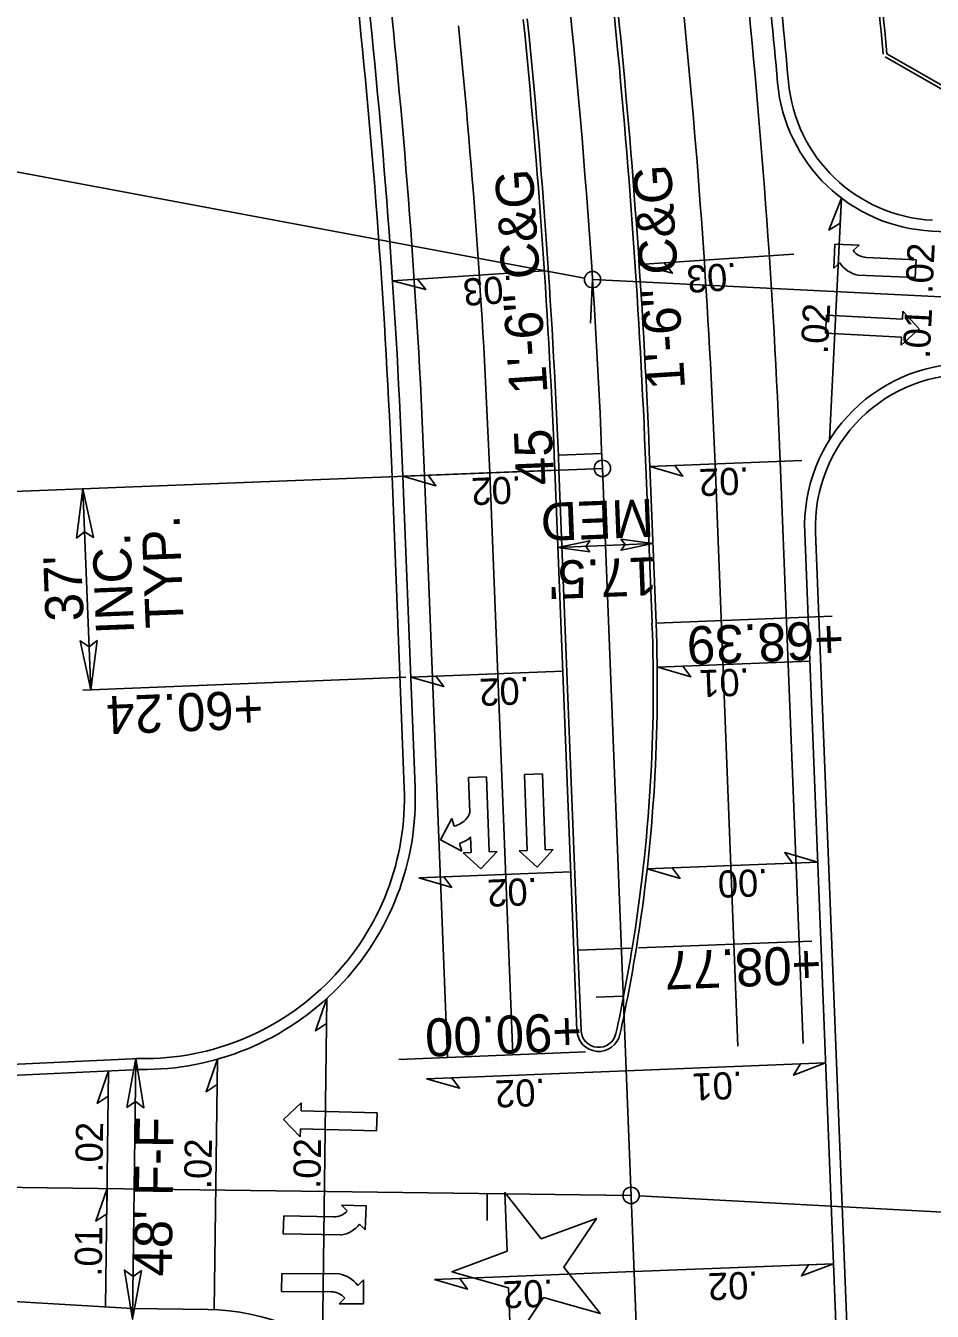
# Model space of a CAD drawing. Extents: x 1627861 to 1629601, y 761281 to 766239.
# Drawn here: x 1628267 to 1628433.8, y 764815.3 to 765051.9 of the extents above; entities that cross this region are included whole.
import ezdxf

# ---------------------------------------------------------------- set-up
doc = ezdxf.new("R2010")
doc.units = 0
for name, color, linetype in [('Exist Property Tie Line Leader', 7, 'Continuous'), ('Exist Property Tie Line Text', 7, 'Continuous'), ('Exist Right of Way Line Leader', 7, 'Continuous'), ('Exist Right of Way Monument Leader', 7, 'Continuous'), ('Exist Right of Way Monument Text', 7, 'Continuous'), ('Exist Utilities Gas Meter CELL', 7, 'Continuous'), ('Exist Utilities Gas Meter Cogo Elevation', 7, 'Continuous'), ('Exist Utilities Gas Meter Cogo Number', 7, 'Continuous'), ('Exist Utilities Gas UG Line', 7, 'Continuous'), ('Exist Utilities Other Unknown UG SUE Text', 7, 'Continuous'), ('Exist Utilities Power UG Cable SUE LOS B Cogo Elevation', 7, 'Continuous'), ('Exist Utilities Power UG Cable SUE LOS B Cogo Point CELL', 7, 'Continuous'), ('Exist Utilities Telephone UG Cable SUE LOS B Cogo Number', 7, 'Continuous'), ('Exist Utilities Water Meter Cogo Elevation', 7, 'Continuous'), ('Exist Utilities Water UG Line SUE LOS B Cogo Number', 7, 'Continuous'), ('Matchline', 7, 'Continuous'), ('Scratch_Level_0', 7, 'Continuous'), ('Typical Terminator CELL', 7, 'Continuous')]:
    doc.layers.add(name, color=color, linetype=linetype)

msp = doc.modelspace()

# ---------------------------------------------------------------- linework, layer by layer
at = {"layer": 'Exist Property Tie Line Text'}
for p, q in [((1628376.95, 764873.29), (1628371.95, 764873.09)), ((1628351.94, 764836.96), (1628351.88, 764831.96))]:
    msp.add_line(p, q, dxfattribs=at)
at = {"layer": 'Exist Right of Way Line Leader'}
for p, q in [((1628369.83, 765005.5), (1628135.9, 765049.17)), ((1628373.12, 764970.45), (1628128.07, 764960.79)), ((1628379.89, 764836.53), (1628534.55, 764828.18))]:
    msp.add_line(p, q, dxfattribs=at)
for centre in [(1628371.3, 765005.2), (1628371.3, 765005.2), (1628373.12, 764970.45), (1628378.39, 764836.61)]:
    msp.add_circle(centre, 1.5, dxfattribs=at)
at = {"layer": 'Exist Right of Way Monument Leader'}
for p, q in [((1628415.72, 765007.3), (1628415.87, 765011.7)), ((1628415.87, 765011.7), (1628420.37, 765011.54)), ((1628420.37, 765011.54), (1628419.27, 765010.54)), ((1628416.82, 765008.3), (1628415.72, 765007.3)), ((1628421.72, 765009.28), (1628430.86, 765008.87)), ((1628430.86, 765008.87), (1628430.71, 765005.57)), ((1628430.71, 765005.57), (1628420.17, 765006.05)), ((1628414.21, 764995.33), (1628414.38, 764998.63)), ((1628414.38, 764998.63), (1628428.36, 764997.9)), ((1628428.36, 764997.9), (1628428.44, 764999.4)), ((1628428.44, 764999.4), (1628431.43, 764996.14)), ((1628428.19, 764994.61), (1628414.21, 764995.33)), ((1628431.43, 764996.14), (1628428.11, 764993.11)), ((1628428.11, 764993.11), (1628428.19, 764994.61)), ((1628348.48, 764913.53), (1628351.78, 764913.65)), ((1628348.71, 764907.09), (1628348.48, 764913.53)), ((1628351.78, 764913.65), (1628352.27, 764899.86)), ((1628358.78, 764914.11), (1628362.08, 764914.22)), ((1628359.29, 764900.12), (1628358.78, 764914.11)), ((1628362.08, 764914.22), (1628362.58, 764900.23)), ((1628343.34, 764902.04), (1628345.4, 764905.97)), ((1628345.4, 764905.97), (1628345.85, 764904.58)), ((1628347.27, 764899.98), (1628343.34, 764902.04)), ((1628346.82, 764901.42), (1628347.27, 764899.98)), ((1628348.98, 764899.74), (1628348.87, 764902.59)), ((1628347.48, 764899.69), (1628348.98, 764899.74)), ((1628350.74, 764896.7), (1628347.48, 764899.69)), ((1628353.77, 764899.92), (1628350.74, 764896.7)), ((1628352.27, 764899.86), (1628353.77, 764899.92)), ((1628357.79, 764900.06), (1628359.29, 764900.12)), ((1628361.1, 764897.03), (1628357.79, 764900.06)), ((1628364.08, 764900.29), (1628361.1, 764897.03)), ((1628362.58, 764900.23), (1628364.08, 764900.29)), ((1628314.45, 764850.56), (1628317.69, 764853.67)), ((1628317.69, 764853.67), (1628317.65, 764852.17)), ((1628317.65, 764852.17), (1628331.64, 764851.78)), ((1628331.64, 764851.78), (1628331.55, 764848.48)), ((1628317.51, 764847.38), (1628314.45, 764850.56)), ((1628317.55, 764848.87), (1628317.51, 764847.38)), ((1628331.55, 764848.48), (1628317.55, 764848.87)), ((1628329.61, 764834.66), (1628325.11, 764834.81)), ((1628325.11, 764834.81), (1628326.14, 764833.74)), ((1628329.46, 764830.26), (1628329.61, 764834.66)), ((1628314.46, 764832.86), (1628314.39, 764829.56)), ((1628323.61, 764832.65), (1628314.46, 764832.86)), ((1628314.39, 764829.56), (1628324.93, 764829.32)), ((1628328.43, 764831.34), (1628329.46, 764830.26)), ((1628314.08, 764818.9), (1628314.1, 764822.2)), ((1628314.1, 764822.2), (1628324.65, 764822.14)), ((1628328.08, 764820.02), (1628329.14, 764821.06)), ((1628329.14, 764821.06), (1628329.16, 764816.66)), ((1628323.23, 764818.84), (1628314.08, 764818.9)), ((1628324.66, 764816.64), (1628325.72, 764817.68)), ((1628329.16, 764816.66), (1628324.66, 764816.64))]:
    msp.add_line(p, q, dxfattribs=at)
for centre, radius, start, end in [((1628421.85, 765012.54), 3.27, 217.7364, 267.3946), ((1628421.19, 765011.18), 5.25, 213.4068, 258.7185), ((1628344.79, 764908.89), 4.43, 283.7683, 314.6218), ((1628346.25, 764907.64), 2.52, 311.1317, 347.4437), ((1628345.77, 764905.74), 4.43, 283.6494, 314.528), ((1628323.69, 764835.9), 3.27, 268.6786, 318.3368), ((1628324.26, 764834.51), 5.25, 277.3547, 322.6664), ((1628323.82, 764816.96), 5.25, 35.6789, 80.9906), ((1628323.22, 764815.59), 3.27, 40.0085, 89.6667)]:
    msp.add_arc(centre, radius, start, end, dxfattribs=at)
at = {"layer": 'Exist Right of Way Monument Text'}
for p, q in [((1628433.78, 765014.15), (1628442.99, 765013.69)), ((1628367.86, 764881.7), (1628364.37, 764970.11)), ((1628383, 764941.97), (1628381.86, 764970.8)), ((1628338.65, 764911.76), (1628336.39, 764969)), ((1628424.43, 764601.84), (1628410.36, 764958.58)), ((1628242.2, 764857.68), (1628288.04, 764859.79)), ((1628287.23, 764859.8), (1628288.04, 764859.79)), ((1628286.66, 764815.8), (1628241.69, 764818.41)), ((1628286.66, 764815.8), (1628300.5, 764815.62))]:
    msp.add_line(p, q, dxfattribs=at)
for centre, radius, start, end in [((1627004.18, 764916.47), 1406.75, 5.09676, 6.1376), ((1627004.18, 764916.47), 1333.25, 2.25819, 6.1376), ((1627004.18, 764916.47), 1378.75, 2.25819, 5.76121), ((1627004.18, 764916.47), 1361.25, 2.25819, 5.76121), ((1628435.25, 765044.11), 30, 185.0968, 267.1852), ((1628440.34, 764959.76), 30, 87.1852, 182.2582), ((1628083.23, 764930.15), 300, 350.7945, 2.2582), ((1628288.69, 764909.79), 50, 269.2561, 2.2582), ((1628299.98, 764775.63), 40, 2.2582, 89.2561)]:
    msp.add_arc(centre, radius, start, end, dxfattribs=at)
at = {"layer": 'Exist Utilities Gas Meter CELL'}
for p, q in [((1628371.3, 765005.2), (1628516.35, 764998.07)), ((1628486.22, 762102.11), (1628373.12, 764970.45)), ((1628151.96, 764839.55), (1628378.39, 764836.61)), ((1628151.96, 764839.55), (1628378.39, 764836.61))]:
    msp.add_line(p, q, dxfattribs=at)
msp.add_arc((1627004.18, 764916.47), 1370, 2.25819, 11.31093, dxfattribs=at)
at = {"layer": 'Exist Utilities Gas Meter Cogo Elevation'}
for p, q in [((1628336.65, 764911.68), (1628334.4, 764968.93)), ((1628426.43, 764601.91), (1628412.36, 764958.65)), ((1628242.11, 764859.68), (1628287.95, 764861.79)), ((1628287.26, 764861.8), (1628288.07, 764861.79))]:
    msp.add_line(p, q, dxfattribs=at)
for centre, radius, start, end in [((1627004.18, 764916.47), 1408.75, 5.09676, 6.1376), ((1627004.18, 764916.47), 1331.25, 2.25819, 6.1376), ((1628435.25, 765044.11), 28, 185.0968, 267.1852), ((1628440.34, 764959.76), 28, 87.1852, 182.2582), ((1628288.69, 764909.79), 48, 269.2561, 2.2582)]:
    msp.add_arc(centre, radius, start, end, dxfattribs=at)
at = {"layer": 'Exist Utilities Gas Meter Cogo Number'}
for points in [[(1628276.3, 764957.63), (1628277.49, 764966.68), (1628279.44, 764957.7), (1628277.8, 764958.79)], [(1628376.54, 764957.43), (1628382.42, 764956.6), (1628376.57, 764955.38), (1628377.29, 764956.45)], [(1628370.81, 764955.08), (1628364.93, 764955.91), (1628370.78, 764957.13), (1628370.06, 764956.07)], [(1628280.14, 764938.77), (1628278.95, 764929.71), (1628276.99, 764938.69), (1628278.64, 764937.61)], [(1628285.59, 764852.82), (1628287.26, 764861.8), (1628288.74, 764852.73), (1628287.16, 764853.9)], [(1628288.3, 764822.78), (1628286.64, 764813.8), (1628285.15, 764822.87), (1628286.74, 764821.7)]]:
    msp.add_lwpolyline(points, close=True, dxfattribs=at)
at = {"layer": 'Exist Utilities Gas UG Line'}
for p, q in [((1628410.07, 764864.59), (1628405.84, 764971.74)), ((1628344.62, 764862.01), (1628340.39, 764969.16)), ((1628356.61, 764862.48), (1628352.38, 764969.64)), ((1628398.07, 764864.11), (1628393.85, 764971.27)), ((1628368.44, 764866.95), (1628367.86, 764881.7))]:
    msp.add_line(p, q, dxfattribs=at)
for centre, radius, start, end in [((1627004.18, 764916.47), 1402.75, 2.25819, 6.1376), ((1627004.18, 764916.47), 1337.25, 2.25819, 6.1376), ((1627004.18, 764916.47), 1390.75, 2.25819, 5.76121), ((1627004.18, 764916.47), 1349.25, 2.25819, 5.76121), ((1628083.23, 764930.15), 300, 347.7022, 350.7945), ((1628372.44, 764867.11), 4, 182.2582, 347.7558)]:
    msp.add_arc(centre, radius, start, end, dxfattribs=at)
at = {"layer": 'Exist Utilities Other Unknown UG SUE Text'}
msp.add_line((1628368.61, 764881.73), (1628369.19, 764866.98), dxfattribs=at)
for centre, radius, start, end in [((1628083.23, 764930.15), 299.25, 347.7034, 350.7654), ((1628372.44, 764867.11), 3.25, 182.2582, 347.7558)]:
    msp.add_arc(centre, radius, start, end, dxfattribs=at)
at = {"layer": 'Exist Utilities Power UG Cable SUE LOS B Cogo Elevation'}
msp.add_lwpolyline([(1628355.85, 764819.61), (1628356.28, 764808.81), (1628362.28, 764817.8), (1628372.71, 764814.86), (1628366, 764823.37), (1628372.01, 764832.38), (1628361.86, 764828.63), (1628355.15, 764837.12), (1628355.58, 764826.31), (1628345.42, 764822.55), (1628355.85, 764819.61)], dxfattribs=at)
at = {"layer": 'Exist Utilities Telephone UG Cable SUE LOS B Cogo Number'}
for p, q in [((1628425.14, 765046.19), (1628442.16, 765036.47)), ((1628425.47, 765046.77), (1628442.49, 765037.05))]:
    msp.add_line(p, q, dxfattribs=at)
for radius in [1426.58, 1427.25]:
    msp.add_arc((1627004.18, 764916.47), radius, 5.23791, 6.15618, dxfattribs=at)
at = {"layer": 'Exist Utilities Water Meter Cogo Elevation'}
for p, q in [((1628371.3, 765005.2), (1628370.91, 764997.21)), ((1628373, 764973.21), (1628365.01, 764972.88))]:
    msp.add_line(p, q, dxfattribs=at)
at = {"layer": 'Exist Utilities Water UG Line SUE LOS B Cogo Number'}
for p, q in [((1628417.1, 765020.22), (1628414.9, 764975.67)), ((1628379.89, 765007.98), (1628408.34, 765009.87)), ((1628334.49, 765004.96), (1628362.43, 765006.82)), ((1628381.86, 764970.8), (1628409.84, 764971.9)), ((1628336.39, 764969.01), (1628364.37, 764970.11)), ((1628411.29, 764934.93), (1628383.32, 764933.83)), ((1628365.83, 764933.14), (1628337.85, 764932.03)), ((1628339.31, 764895.06), (1628367.29, 764896.17)), ((1628381.36, 764896.72), (1628412.75, 764897.96)), ((1628322.41, 764872.86), (1628321.58, 764809.3)), ((1628302.26, 764861.66), (1628301.66, 764815.59)), ((1628377.49, 764859.54), (1628414.21, 764860.99)), ((1628282.23, 764859.52), (1628281.67, 764816.09)), ((1628340.77, 764858.09), (1628377.49, 764859.54)), ((1628378.95, 764822.57), (1628342.23, 764821.12)), ((1628415.67, 764824.02), (1628378.95, 764822.57))]:
    msp.add_line(p, q, dxfattribs=at)
at = {"layer": 'Matchline'}
for p, q in [((1628368.61, 764881.73), (1628365.12, 764970.14)), ((1628382.25, 764941.94), (1628381.11, 764970.77)), ((1628368.61, 764881.73), (1628378.6, 764882.13))]:
    msp.add_line(p, q, dxfattribs=at)
for centre, radius, start, end in [((1627004.18, 764916.47), 1378, 2.25819, 5.76102), ((1627004.18, 764916.47), 1362, 2.25819, 5.76102), ((1628083.23, 764930.15), 299.25, 350.7654, 2.2582)]:
    msp.add_arc(centre, radius, start, end, dxfattribs=at)
at = {"layer": 'Scratch_Level_0'}
for p, q in [((1628278.95, 764929.71), (1628277.49, 764966.68)), ((1628364.93, 764955.91), (1628382.42, 764956.6)), ((1628415.4, 764943.25), (1628383, 764941.97)), ((1628411.67, 764883.43), (1628379.77, 764882.17)), ((1628370.03, 764863.01), (1628335.63, 764861.65)), ((1628286.64, 764813.8), (1628287.26, 764861.8))]:
    msp.add_line(p, q, dxfattribs=at)
msp.add_lwpolyline([(1628277.47, 764929.65), (1628336.97, 764932)], dxfattribs=at)
at = {"layer": 'Typical Terminator CELL'}
for points in [[(1628417.1, 765020.22), (1628414.8, 765014.33), (1628416.87, 765015.61)], [(1628379.89, 765007.98), (1628386.01, 765006.38), (1628384.5, 765008.29)], [(1628334.49, 765004.96), (1628340.61, 765003.36), (1628339.1, 765005.27)], [(1628336.39, 764969.01), (1628342.47, 764967.24), (1628341.02, 764969.19)], [(1628381.86, 764970.8), (1628387.93, 764969.04), (1628386.48, 764970.98)], [(1628383.32, 764933.83), (1628389.39, 764932.07), (1628387.94, 764934.01)], [(1628337.85, 764932.03), (1628343.93, 764930.27), (1628342.47, 764932.22)], [(1628412.75, 764897.96), (1628406.68, 764899.72), (1628408.13, 764897.78)], [(1628381.36, 764896.72), (1628387.43, 764894.96), (1628385.98, 764896.9)], [(1628339.31, 764895.06), (1628345.38, 764893.3), (1628343.93, 764895.25)], [(1628322.41, 764872.86), (1628320.33, 764866.89), (1628322.35, 764868.24)], [(1628302.26, 764861.66), (1628300.18, 764855.69), (1628302.2, 764857.04)], [(1628414.21, 764860.99), (1628408.29, 764858.75), (1628409.59, 764860.81)], [(1628282.23, 764859.52), (1628280.15, 764853.55), (1628282.17, 764854.9)], [(1628340.77, 764858.09), (1628346.84, 764856.33), (1628345.39, 764858.27)], [(1628281.95, 764837.87), (1628279.87, 764831.89), (1628281.89, 764833.24)], [(1628415.67, 764824.02), (1628409.75, 764821.78), (1628411.05, 764823.83)], [(1628342.23, 764821.12), (1628348.3, 764819.36), (1628346.85, 764821.3)]]:
    msp.add_lwpolyline(points, close=True, dxfattribs=at)

# ---------------------------------------------------------------- texts
at = {"layer": 'Exist Property Tie Line Leader'}
msp.add_text('45', height=7, rotation=92.3736, dxfattribs=at).set_placement((1628364.23, 764967.47))
at = {"layer": 'Exist Utilities Power UG Cable SUE LOS B Cogo Point CELL'}
for s, rotation, p in [('MED', 182.2582, (1628382.44, 764964.86)), ('TYP.', 92.2582, (1628296.07, 764941.18)), ('INC.', 92.2582, (1628286.93, 764940.04)), ("37'", 92.2582, (1628277.65, 764942.41)), ("17.5'", 182.2582, (1628383.04, 764954.15)), ("48' F-F", 89.2561, (1628293.85, 764821.65))]:
    msp.add_text(s, height=7, rotation=rotation, dxfattribs=at).set_placement(p)
at = {"layer": 'Exist Utilities Water UG Line SUE LOS B Cogo Number'}
for s, rotation, p in [('.02', 87.1852, (1628433.86, 765002.54)), ('.03', 183.8056, (1628397.78, 765008.34)), ('.03', 184.0052, (1628356.58, 765005.98)), ('.02', 87.1852, (1628414.61, 764991.43)), ('.01', 87.1852, (1628433.36, 764990.58)), ('.02', 182.2582, (1628400.09, 764970.68)), ('.02', 182.2582, (1628358.19, 764969.03)), ('.01', 182.2582, (1628400.13, 764933.66)), ('.02', 182.2582, (1628359.65, 764932.06)), ('.00', 182.2582, (1628403.55, 764896.74)), ('.02', 182.2582, (1628361.11, 764895.09)), ('.02', 182.2582, (1628362.56, 764858.12)), ('.01', 182.6369, (1628398.86, 764859.44)), ('.02', 89.1874, (1628281.11, 764840.79)), ('.02', 89.1874, (1628301.13, 764837.74)), ('.02', 89.1874, (1628321.22, 764837.79)), ('.01', 89.1874, (1628280.96, 764821.62)), ('.02', 182.2582, (1628401.74, 764822.63)), ('.02', 182.2582, (1628364.02, 764821.15))]:
    msp.add_text(s, height=5, rotation=rotation, dxfattribs=at).set_placement(p)
at = {"layer": 'Scratch_Level_0'}
for s, rotation, p in [('1\'-6" C&G', 93.8303, (1628363.04, 764984.34)), ('1\'-6" C&G', 93.6551, (1628388.35, 764985.16)), ('+68.39', 182.2582, (1628417.42, 764942.44)), ('+60.24', 182.2582, (1628310.56, 764929.61)), ('+08.77', 182.2582, (1628413.27, 764882.61)), ('+90.00', 182.2582, (1628369.22, 764870.25))]:
    msp.add_text(s, height=7, rotation=rotation, dxfattribs=at).set_placement(p)

doc.saveas('drawing.dxf')
